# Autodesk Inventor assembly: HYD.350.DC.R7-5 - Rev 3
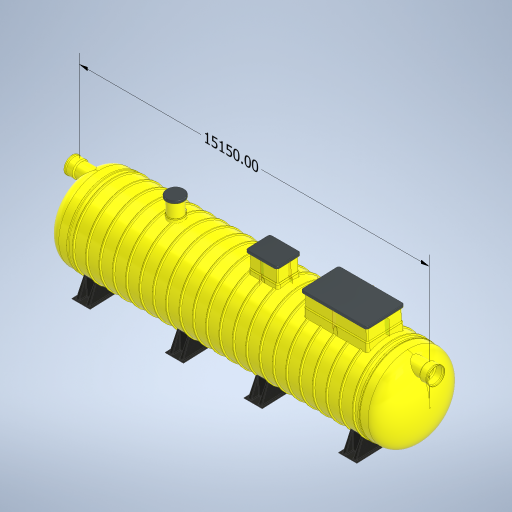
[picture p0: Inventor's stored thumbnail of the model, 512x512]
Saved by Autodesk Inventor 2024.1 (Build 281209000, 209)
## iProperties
Created: 2023-08
Part Number: HYD.350.DC.R7-5 - Rev 3
Document SubType Name: Assembly
Designer: macga
Author: macga
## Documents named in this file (47)
- D:\$ Protector Vault\Workspace\Automation Files\1. Protector Stardard Products\HydroProtectors\FAMILY\HYD.350 - Vernon\HYD.350.DC.R7-5 - Rev 3.iam
- D:\$ Protector Vault\Workspace\1. Protector Stardard Products\HydroProtectors\FAMILY\HORIZONTAL TANK - IPART\HORIZONTAL TANK - IPART.ipt
- D:\$ Protector Vault\Workspace\1. Protector Stardard Products\HydroProtectors\FAMILY\DOME - IPART\DOME - IPART.ipt
- D:\$ Protector Vault\Workspace\1. Protector Stardard Products\HydroProtectors\FAMILY\FOOT - IPART\FRP Foot - IPART.ipt
- D:\$ Protector Vault\Workspace\1. Protector Stardard Products\HydroProtectors\FAMILY\ACDTUBE - IPART\ACDTUBE - IPART.ipt
- D:\$ Protector Vault\Workspace\1. Protector Stardard Products\HydroProtectors\FAMILY\ACD FLOAT VALVE - IPART\ACD.FloatValve - IASSY.iam
- D:\$ Protector Vault\Workspace\1. Protector Stardard Products\HydroProtectors\FAMILY\OUTLET ELBOW - IPART\OUTLET ELBOW - IPART.ipt
- D:\$ Protector Vault\Workspace\1. Protector Stardard Products\HydroProtectors\Coalescer Guide Rail.ipt
- D:\$ Protector Vault\Workspace\1. Protector Stardard Products\HydroProtectors\Upper Guide Rai Braket.ipt
- D:\$ Protector Vault\Workspace\1. Protector Stardard Products\Standard Components\Flanged Vent.ipt
- D:\$ Protector Vault\Workspace\1. Protector Stardard Products\Xtremeprotector\Vault\Chain.ipt
- D:\$ Protector Vault\Workspace\1. Protector Stardard Products\Xtremeprotector\Vault\Lifting Eye.ipt
- D:\$ Protector Vault\Workspace\1. Protector Stardard Products\HydroProtectors\FAMILY\ACDTUBE - IPART\ACDTUBE - IPART\ACDTUBE.750-3300.ipt
- D:\$ Protector Vault\Workspace\1. Protector Stardard Products\HydroProtectors\FAMILY\ACD FLOAT VALVE - IPART\ACD.FloatValve - IASSY\ACD.FVALVE.750.ASSY.iam
- D:\$ Protector Vault\Workspace\1. Protector Stardard Products\HydroProtectors\FAMILY\SU.900X1200.ManwayRiserAdaptor - IPART\SU.900X1200.ManwayRiserAdapator - IPART.ipt
- D:\$ Protector Vault\Workspace\1. Protector Stardard Products\Standard Components\900x1200x600 Manway Riser.ipt
- D:\$ Protector Vault\Workspace\1. Protector Stardard Products\Standard Components\900x1200 Manway Cover ST\900x900 Manway Cover Class D ST-02.ipt
- D:\$ Protector Vault\Workspace\1. Protector Stardard Products\Standard Components\900x1200 Manway Cover ST.ipt
- D:\$ Protector Vault\Workspace\1. Protector Stardard Products\HydroProtectors\FAMILY\DOME - IPART\DOME - IPART\SU.DOME.3500-22.ipt
- D:\$ Protector Vault\Workspace\1. Protector Stardard Products\HydroProtectors\FAMILY\FOOT - IPART\FRP Foot - IPART\SU.HS.FOOT.3500.ipt
- D:\$ Protector Vault\Workspace\1. Protector Stardard Products\HydroProtectors\FAMILY\HYD.BAFFLE - IPART\SU.BAFFLE.3500\SU.BAFFLE.3500-1100x775x610.ipt
- D:\$ Protector Vault\Workspace\1. Protector Stardard Products\HydroProtectors\FAMILY\HYD.BAFFLE - IPART\SU.BAFFLE.3500.ipt
- D:\$ Protector Vault\Workspace\1. Protector Stardard Products\HydroProtectors\FAMILY\ACD Base - IPART\SU.ACDBASE.3500\SU.ACDBASE.3500-700,1100.ipt
- D:\$ Protector Vault\Workspace\1. Protector Stardard Products\HydroProtectors\FAMILY\ACD Base - IPART\SU.ACDBASE.3500.ipt
- D:\$ Protector Vault\Workspace\1. Protector Stardard Products\HydroProtectors\FAMILY\SU.900X1200.ManwayRiserAdaptor - IPART\SU.900X1200.ManwayRiserAdapator - IPART\SU.900x1200ManwayRiserAdapter.3500.ipt
- D:\$ Protector Vault\Workspace\1. Protector Stardard Products\HydroProtectors\FAMILY\Coalescer Guide Rail-0124.ipt
- D:\$ Protector Vault\Workspace\1. Protector Stardard Products\HydroProtectors\FAMILY\Coalescer Guide Rail-0125.ipt
- D:\$ Protector Vault\Workspace\1. Protector Stardard Products\HydroProtectors\FAMILY\CF.BASE - IPART\CF BASE PENTA  2.0 - IPART.ipt
- D:\$ Protector Vault\Workspace\1. Protector Stardard Products\Standard Components\1500x2700 Manway Adaptor\SU.1500x2700ManwayRiserAdaptor.3500.ipt
- D:\$ Protector Vault\Workspace\1. Protector Stardard Products\Standard Components\1500x2700 Manway Adaptor.ipt
- D:\$ Protector Vault\Workspace\1. Protector Stardard Products\Standard Components\1500x2700x600 Manway Riser.ipt
- D:\$ Protector Vault\Workspace\1. Protector Stardard Products\Standard Components\1500x2700 Manway Cover ST\1500x2700 Manway Cover Class D ST-02.ipt
- D:\$ Protector Vault\Workspace\1. Protector Stardard Products\Standard Components\1500x2700 Manway Cover ST.ipt
- D:\$ Protector Vault\Workspace\1. Protector Stardard Products\HydroProtectors\FAMILY\COALESCER FILTER - IPART\CF-R7.iam
- D:\$ Protector Vault\Workspace\1. Protector Stardard Products\Xtremeprotector\Vault\Chain\Chain-55.ipt
- D:\$ Protector Vault\Workspace\1. Protector Stardard Products\HydroProtectors\FAMILY\CF.BASE - IPART\CF BASE PENTA  2.0 - IPART\SU.CFBASE.3500.B2.5-R7-OP.450.ipt
- D:\$ Protector Vault\Workspace\1. Protector Stardard Products\HydroProtectors\FAMILY\HORIZONTAL TANK - IPART\HORIZONTAL TANK - IPART\WIN.HB.3500x12650L-22.ipt
- D:\$ Protector Vault\Workspace\1. Protector Stardard Products\HydroProtectors\FAMILY\COALESCER FILTER - IPART\CF-R7_MIR7.iam
- D:\$ Protector Vault\Workspace\1. Protector Stardard Products\Xtremeprotector\Vault\Lifting Eye_MIR13.ipt
- D:\$ Protector Vault\Workspace\1. Protector Stardard Products\HydroProtectors\Upper Guide Rai Braket_MIR13.ipt
- D:\$ Protector Vault\Workspace\1. Protector Stardard Products\600 Dia Adaptor, Riser, Cover Assy - 3500\600 Dia Adaptor, Riser, Class D Cover Assy -3000.iam
- D:\$ Protector Vault\Workspace\1. Protector Stardard Products\600 Dia Adaptor, Riser, Cover Assy - 3500.iam
- D:\$ Protector Vault\Workspace\1. Protector Stardard Products\StormProtector\600 Storm Pro Inlet Elbow.ipt
- D:\$ Protector Vault\Workspace\1. Protector Stardard Products\HydroProtectors\FAMILY\OUTLET ELBOW - IPART\OUTLET ELBOW - IPART\OutletPipeElbow.600D-100DCoupling.ipt
- D:\$ Protector Vault\Workspace\1. Protector Stardard Products\StormProtector\600 Storm Pro Pipe and Socket.ipt
- D:\$ Protector Vault\Workspace\1. Protector Stardard Products\StormProtector\ISO 4065 Pipe DN630x15.4xS20 - 3000.ipt
- D:\$ Protector Vault\Workspace\1. Protector Stardard Products\Trade Waste Sampling Point Assembly 600.iam
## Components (51 placed, 30 different names)
1. WIN.HB.3500x12650L-22:1
2. SU.DOME.3500-22:1 — Mate:1, Mate:3, Mate:78, Mate:93, Mate:176, Angle:5, Angle:11
3. 600 Storm Pro Inlet Elbow:1 — Mate:176, Angle:5, Tangent:140
4. SU.DOME.3500-22:2 — Mate:2, Mate:4, Mate:94, Mate:172
5. SU.HS.FOOT.3500:1 — Mate:74, Mate:75, Angle:7
6. SU.HS.FOOT.3500:2 — Mate:76, Mate:77, Angle:10
7. SU.HS.FOOT.3500:3 — Mate:149, Angle:9, Mate:232
8. SU.HS.FOOT.3500:4 — Mate:147, Mate:148, Angle:8
9. SU.BAFFLE.3500-1100x775x610:1
10. SU.ACDBASE.3500-700,1100:1 — Mate:14, Mate:79, Flush:179, Angle:3, Mate:185
11. ACDTUBE.750-3300:1 — Mate:14, Mate:208
12. ACD.FVALVE.750.ASSY:1 [sub-assembly] — Mate:208
13. SU.CFBASE.3500.B2.5-R7-OP.450:1 — Mate:16, Flush:173, Mate:154, Mate:221, Mate:222, Mate:223, Mate:247, Mate:248
14. CF-R7:2 [sub-assembly] — Mate:86, Tangent:4
15. CF-R7:1 [sub-assembly] — Mate:154, Mate:157, Tangent:126
16. ISO 4065 Pipe DN630x15.4xS20 - 3000:1 — Mate:247, Mate:248, Mate:249, Mate:250
17. OutletPipeElbow.600D-100DCoupling:2 — Mate:249, Mate:250, Mate:251, Mate:252
18. 600 Storm Pro Pipe and Socket:1 — Mate:251, Mate:252, Mate:253
19. 900x1200x600 Manway Riser:1 — Mate:187, Mate:188, Mate:189
20. 900x900 Manway Cover Class D ST-02:1 — Flush:222
21. Flanged Vent:3 — Mate:194, Mate:195
22. Flanged Vent:4
23. SU.900x1200ManwayRiserAdapter.3500:1
24. Chain-55:1 — Mate:157, Tangent:126, Tangent:127
25. Chain-55:2 — Mate:86, Tangent:4, Tangent:128
26. Lifting Eye:1 — Tangent:127, Mate:160
27. Lifting Eye:2 — Tangent:128, Mate:161
28. Coalescer Guide Rail-0124:1 — Mate:62, Mate:63, Flush:5
29. Coalescer Guide Rail-0125:2 — Mate:64, Mate:65, Flush:6
30. Upper Guide Rai Braket:1 — Mate:62, Mate:63, Flush:5, Mate:160
31. Upper Guide Rai Braket:2 — Mate:64, Mate:65, Flush:6, Mate:161
32. SU.1500x2700ManwayRiserAdaptor.3500:1
33. 1500x2700x600 Manway Riser:1 — Mate:233, Mate:234, Mate:235
34. 1500x2700 Manway Cover Class D ST-02:1 — Angle:17
35. CF-R7:3 [sub-assembly] — Mate:236, Tangent:130, Tangent:135
36. Coalescer Guide Rail-0124:5 — Mate:221, Mate:222, Mate:223
37. Upper Guide Rai Braket:3
38. Chain-55:3 — Tangent:129, Mate:236, Tangent:135
39. Lifting Eye:3 — Tangent:129, Mate:233, Mate:234, Mate:235, Tangent:130
40. CF-R7_MIR7:1 [sub-assembly] — Mate:244, Tangent:139, Flush:221
41. CF-R7_MIR7:2 [sub-assembly] — Tangent:138, Mate:243, Flush:221
42. Chain-55:4 — Tangent:136, Tangent:138, Mate:243
43. Chain-55:5 — Tangent:137, Mate:244, Tangent:139
44. Lifting Eye_MIR13:1 — Tangent:136, Mate:241
45. Lifting Eye_MIR13:2 — Tangent:137, Mate:242
46. Coalescer Guide Rail-0124:6 — Flush:219, Mate:237, Mate:238
47. Coalescer Guide Rail-0125:7 — Flush:220, Mate:239, Mate:240
48. Upper Guide Rai Braket_MIR13:1 — Flush:219, Mate:237, Mate:238, Mate:241
49. Upper Guide Rai Braket_MIR13:2 — Flush:220, Mate:239, Mate:240, Mate:242
50. 600 Dia Adaptor, Riser, Class D Cover Assy -3000:1 [sub-assembly] — Mate:245, Flush:222, Mate:246
51. Trade Waste Sampling Point Assembly 600:1 [sub-assembly] — Mate:253, Angle:17
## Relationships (88: Mate 60, Tangent 12, Flush 8, Angle 8)
- Mate:1: SU.DOME.3500-22:1
- Mate:2: SU.DOME.3500-22:2
- Mate:3: SU.DOME.3500-22:1
- Mate:4: SU.DOME.3500-22:2
- Mate:14: SU.ACDBASE.3500-700,1100:1 ↔ ACDTUBE.750-3300:1
- Mate:16: SU.CFBASE.3500.B2.5-R7-OP.450:1
- Flush:173: SU.CFBASE.3500.B2.5-R7-OP.450:1
- Mate:62: Coalescer Guide Rail-0124:1 ↔ Upper Guide Rai Braket:1
- Mate:63: Coalescer Guide Rail-0124:1 ↔ Upper Guide Rai Braket:1
- Flush:5: Coalescer Guide Rail-0124:1 ↔ Upper Guide Rai Braket:1
- Mate:64: Coalescer Guide Rail-0125:2 ↔ Upper Guide Rai Braket:2
- Mate:65: Coalescer Guide Rail-0125:2 ↔ Upper Guide Rai Braket:2
- Flush:6: Coalescer Guide Rail-0125:2 ↔ Upper Guide Rai Braket:2
- Mate:74: SU.HS.FOOT.3500:1
- Mate:75: SU.HS.FOOT.3500:1
- Mate:76: SU.HS.FOOT.3500:2
- Mate:77: SU.HS.FOOT.3500:2
- Mate:78: SU.DOME.3500-22:1
- Mate:79: SU.ACDBASE.3500-700,1100:1
- Mate:86: CF-R7:2 ↔ Chain-55:2
- Tangent:4: CF-R7:2 ↔ Chain-55:2
- Mate:93: SU.DOME.3500-22:1
- Mate:94: SU.DOME.3500-22:2
- Flush:179: SU.ACDBASE.3500-700,1100:1
- Mate:208: ACDTUBE.750-3300:1 ↔ ACD.FVALVE.750.ASSY:1
- Angle:3: SU.ACDBASE.3500-700,1100:1
- Mate:147: SU.HS.FOOT.3500:4
- Mate:148: SU.HS.FOOT.3500:4
- Mate:149: SU.HS.FOOT.3500:3
- Mate:176: SU.DOME.3500-22:1 ↔ 600 Storm Pro Inlet Elbow:1
- Angle:5: SU.DOME.3500-22:1 ↔ 600 Storm Pro Inlet Elbow:1
- Angle:7: SU.HS.FOOT.3500:1
- Angle:8: SU.HS.FOOT.3500:4
- Angle:9: SU.HS.FOOT.3500:3
- Angle:10: SU.HS.FOOT.3500:2
- Angle:11: SU.DOME.3500-22:1
- Mate:154: SU.CFBASE.3500.B2.5-R7-OP.450:1 ↔ CF-R7:1
- Mate:157: CF-R7:1 ↔ Chain-55:1
- Tangent:126: CF-R7:1 ↔ Chain-55:1
- Tangent:127: Chain-55:1 ↔ Lifting Eye:1
- Tangent:128: Chain-55:2 ↔ Lifting Eye:2
- Mate:160: Lifting Eye:1 ↔ Upper Guide Rai Braket:1
- Mate:161: Lifting Eye:2 ↔ Upper Guide Rai Braket:2
- Mate:172: SU.DOME.3500-22:2
- Mate:185: SU.ACDBASE.3500-700,1100:1
- Mate:187: 900x1200x600 Manway Riser:1
- Mate:188: 900x1200x600 Manway Riser:1
- Mate:189: 900x1200x600 Manway Riser:1
- Mate:194: Flanged Vent:3
- Mate:195: Flanged Vent:3
- Mate:221: SU.CFBASE.3500.B2.5-R7-OP.450:1 ↔ Coalescer Guide Rail-0124:5
- Mate:222: SU.CFBASE.3500.B2.5-R7-OP.450:1 ↔ Coalescer Guide Rail-0124:5
- Mate:223: SU.CFBASE.3500.B2.5-R7-OP.450:1 ↔ Coalescer Guide Rail-0124:5
- Mate:232: SU.HS.FOOT.3500:3
- Tangent:129: Chain-55:3 ↔ Lifting Eye:3
- Mate:233: 1500x2700x600 Manway Riser:1 ↔ Lifting Eye:3
- Mate:234: 1500x2700x600 Manway Riser:1 ↔ Lifting Eye:3
- Mate:235: 1500x2700x600 Manway Riser:1 ↔ Lifting Eye:3
- Mate:236: CF-R7:3 ↔ Chain-55:3
- Tangent:130: CF-R7:3 ↔ Lifting Eye:3
- Tangent:135: CF-R7:3 ↔ Chain-55:3
- Flush:219: Coalescer Guide Rail-0124:6 ↔ Upper Guide Rai Braket_MIR13:1
- Mate:237: Coalescer Guide Rail-0124:6 ↔ Upper Guide Rai Braket_MIR13:1
- Mate:238: Coalescer Guide Rail-0124:6 ↔ Upper Guide Rai Braket_MIR13:1
- Flush:220: Coalescer Guide Rail-0125:7 ↔ Upper Guide Rai Braket_MIR13:2
- Mate:239: Coalescer Guide Rail-0125:7 ↔ Upper Guide Rai Braket_MIR13:2
- Mate:240: Coalescer Guide Rail-0125:7 ↔ Upper Guide Rai Braket_MIR13:2
- Tangent:136: Chain-55:4 ↔ Lifting Eye_MIR13:1
- Mate:241: Lifting Eye_MIR13:1 ↔ Upper Guide Rai Braket_MIR13:1
- Tangent:137: Chain-55:5 ↔ Lifting Eye_MIR13:2
- Mate:242: Lifting Eye_MIR13:2 ↔ Upper Guide Rai Braket_MIR13:2
- Tangent:138: CF-R7_MIR7:2 ↔ Chain-55:4
- Mate:243: CF-R7_MIR7:2 ↔ Chain-55:4
- Mate:244: CF-R7_MIR7:1 ↔ Chain-55:5
- Tangent:139: CF-R7_MIR7:1 ↔ Chain-55:5
- Flush:221: CF-R7_MIR7:1 ↔ CF-R7_MIR7:2
- Mate:245: 600 Dia Adaptor, Riser, Class D Cover Assy -3000:1
- Flush:222: 900x900 Manway Cover Class D ST-02:1 ↔ 600 Dia Adaptor, Riser, Class D Cover Assy -3000:1
- Mate:246: 600 Dia Adaptor, Riser, Class D Cover Assy -3000:1
- Mate:247: SU.CFBASE.3500.B2.5-R7-OP.450:1 ↔ ISO 4065 Pipe DN630x15.4xS20 - 3000:1
- Mate:248: SU.CFBASE.3500.B2.5-R7-OP.450:1 ↔ ISO 4065 Pipe DN630x15.4xS20 - 3000:1
- Mate:249: ISO 4065 Pipe DN630x15.4xS20 - 3000:1 ↔ OutletPipeElbow.600D-100DCoupling:2
- Mate:250: ISO 4065 Pipe DN630x15.4xS20 - 3000:1 ↔ OutletPipeElbow.600D-100DCoupling:2
- Mate:251: OutletPipeElbow.600D-100DCoupling:2 ↔ 600 Storm Pro Pipe and Socket:1
- Mate:252: OutletPipeElbow.600D-100DCoupling:2 ↔ 600 Storm Pro Pipe and Socket:1
- Tangent:140: 600 Storm Pro Inlet Elbow:1
- Mate:253: 600 Storm Pro Pipe and Socket:1 ↔ Trade Waste Sampling Point Assembly 600:1
- Angle:17: 1500x2700 Manway Cover Class D ST-02:1 ↔ Trade Waste Sampling Point Assembly 600:1
## Named parameters: d484_d77 = 35 mm, d485_d75 = 0, d486_d76 = 1 mm, d507_d341 = 0
